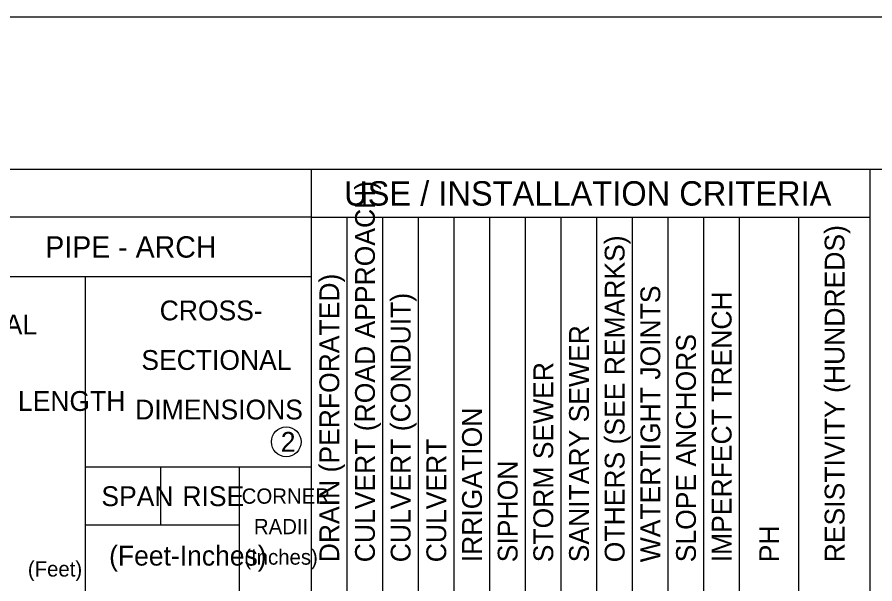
# Model space of a CAD drawing. Extents: x -1700 to 0, y 0 to 1100.
# Drawn here: x -1368.4 to -1086.9, y 914.1 to 1100 of the extents above; entities that cross this region are included whole.
import ezdxf

# ---------------------------------------------------------------- set-up
doc = ezdxf.new("R2010")
doc.units = 0
for name, color, linetype in [('#plot_shape', 7, 'Continuous'), ('P_ODOT_PLAN_Border', 7, 'Continuous'), ('P_ODOT_PLAN_General', 7, 'Continuous'), ('P_RDWY_PLAN_NotesTx', 7, 'Continuous')]:
    doc.layers.add(name, color=color, linetype=linetype)

msp = doc.modelspace()

# ---------------------------------------------------------------- linework, layer by layer
at = {"layer": '#plot_shape'}
msp.add_lwpolyline([(-1700, 0), (0, 0), (0, 1100), (-1700, 1100)], close=True, dxfattribs=at)
at = {"layer": 'P_ODOT_PLAN_Border'}
msp.add_lwpolyline([(-1625, 50), (-25, 50), (-25, 1050), (-1625, 1050)], close=True, dxfattribs=at)
at = {"layer": 'P_ODOT_PLAN_General'}
for p, q in [((-1271.83, 312.45), (-1271.83, 1050)), ((-1088.42, 312.45), (-1088.42, 1050)), ((-1271.83, 1034.39), (-1574.27, 1034.39)), ((-1271.83, 1034.39), (-1088.42, 1034.39)), ((-1260.12, 312.45), (-1260.12, 1034.39)), ((-1248.42, 312.45), (-1248.42, 1034.39)), ((-1236.71, 312.45), (-1236.71, 1034.39)), ((-1225, 312.45), (-1225, 1034.39)), ((-1213.3, 312.45), (-1213.3, 1034.39)), ((-1201.59, 312.45), (-1201.59, 1034.39)), ((-1189.88, 312.45), (-1189.88, 1034.39)), ((-1178.17, 312.45), (-1178.17, 1034.39)), ((-1166.47, 312.45), (-1166.47, 1034.39)), ((-1154.76, 312.45), (-1154.76, 1034.39)), ((-1143.05, 312.45), (-1143.05, 1034.39)), ((-1131.35, 312.45), (-1131.35, 1034.39)), ((-1111.83, 312.45), (-1111.83, 1034.39)), ((-1271.83, 1014.88), (-1398.66, 1014.88)), ((-1345.98, 312.45), (-1345.98, 1014.88)), ((-1271.83, 952.44), (-1345.98, 952.44)), ((-1321.23, 933.35), (-1321.23, 952.44)), ((-1295.47, 312.45), (-1295.47, 952.44)), ((-1295.47, 933.35), (-1345.98, 933.35))]:
    msp.add_line(p, q, dxfattribs=at)
at = {"layer": 'P_RDWY_PLAN_NotesTx'}
msp.add_circle((-1280.11, 960.72), 4.88, dxfattribs=at)

# ---------------------------------------------------------------- texts
for s, height, p in [('USE / INSTALLATION CRITERIA', 8, (-1261.1, 1038.2)), ('PIPE - ARCH', 7, (-1359.19, 1021.13)), ('CROSS-', 6.5, (-1321.65, 1000.56)), ('HELICAL', 6.5, (-1398.1, 995.96)), ('SECTIONAL', 6.5, (-1327.66, 984.31)), ('LENGTH', 6.5, (-1368.17, 970.86)), ('DIMENSIONS', 6.5, (-1329.7, 968.06)), ('2', 6.5, (-1281.9, 957.47)), ('SPAN', 6.5, (-1340.78, 939.64)), ('RISE', 6.5, (-1314.19, 939.64)), ('CORNER', 5, (-1294.73, 940.43)), ('RADII', 5, (-1290.72, 930.43)), ('(Feet-Inches)', 6.5, (-1338.24, 920.13)), ('(Inches)', 5, (-1293.89, 920.43)), ('(Feet)', 5, (-1364.92, 916.54))]:
    msp.add_text(s, height=height, dxfattribs=at).set_placement(p)
for s, p in [('CULVERT (ROAD APPROACH)', (-1251.02, 921.22)), ('RESISTIVITY (HUNDREDS)', (-1096.88, 921.22)), ('OTHERS (SEE REMARKS)', (-1169.07, 921.22)), ('DRAIN (PERFORATED)', (-1262.73, 921.22)), ('WATERTIGHT JOINTS', (-1157.36, 921.22)), ('CULVERT (CONDUIT)', (-1239.31, 921.22)), ('IMPERFECT TRENCH', (-1133.95, 921.22)), ('SANITARY SEWER', (-1180.78, 921.22)), ('SLOPE ANCHORS', (-1145.66, 921.22)), ('STORM SEWER', (-1192.49, 921.22)), ('IRRIGATION', (-1215.9, 921.22)), ('CULVERT', (-1227.61, 921.22)), ('SIPHON', (-1204.19, 921.22)), ('PH', (-1118.34, 921.22))]:
    msp.add_text(s, height=6.5, rotation=90, dxfattribs=at).set_placement(p)

doc.saveas('drawing.dxf')
